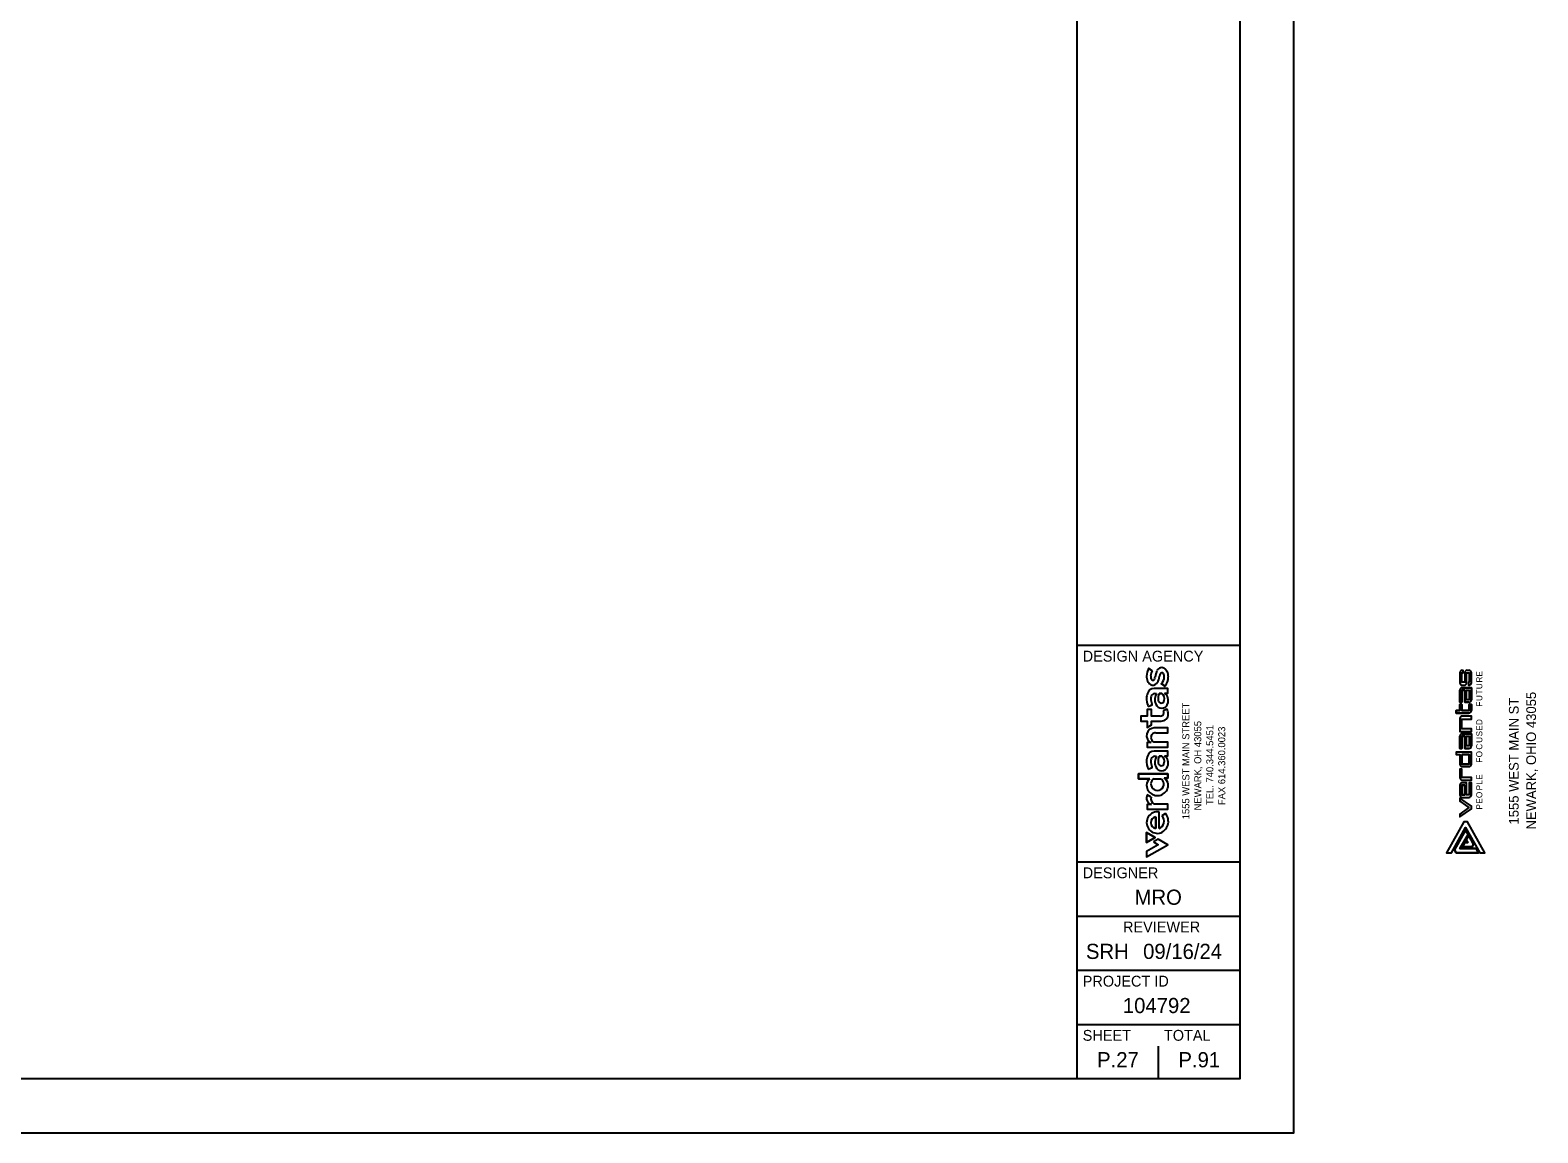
# Model space of a CAD drawing. Extents: x 0 to 36.3, y 0 to 22.
# Drawn here: x 22.33 to 36.25, y 0 to 10.18 of the extents above; entities that cross this region are included whole.
import ezdxf

# ---------------------------------------------------------------- set-up
doc = ezdxf.new("R2010")
doc.units = 0
for name, color, linetype in [('CS-ANNO-TTLB-LOGO', 7, 'Continuous'), ('Default', 7, 'Continuous'), ('SH_Border', 7, 'Continuous'), ('SH_Cut_Line', 7, 'Continuous'), ('SH_Data', 7, 'Continuous'), ('SH_Text', 7, 'Continuous')]:
    doc.layers.add(name, color=color, linetype=linetype)

msp = doc.modelspace()

# ---------------------------------------------------------------- linework, layer by layer
at = {"layer": 'CS-ANNO-TTLB-LOGO'}
for p, q in [((35.533, 4.247), (35.533, 4.154)), ((35.564, 4.269), (35.555, 4.269)), ((35.617, 4.269), (35.6, 4.269)), ((35.64, 4.154), (35.64, 4.247)), ((35.533, 3.974), (35.533, 4.086)), ((35.555, 4.131), (35.572, 4.131)), ((35.533, 3.549), (35.533, 3.661)), ((35.555, 3.38), (35.617, 3.38)), ((35.533, 3.209), (35.533, 3.119)), ((35.64, 3.119), (35.64, 3.231)), ((35.555, 3.096), (35.617, 3.096))]:
    msp.add_line(p, q, dxfattribs=at)
for points in [[(35.578, 4.247), (35.578, 4.159), (35.552, 4.159), (35.552, 4.247), (35.564, 4.247), (35.564, 4.269)], [(35.595, 4.154), (35.595, 4.247), (35.62, 4.247), (35.62, 4.159), (35.611, 4.159), (35.611, 4.131), (35.617, 4.131)], [(35.617, 3.974), (35.578, 3.974), (35.578, 4.086), (35.552, 4.086), (35.552, 3.974), (35.533, 3.974)], [(35.555, 4.109), (35.64, 4.109), (35.64, 3.996)], [(35.498, 3.898), (35.533, 3.898), (35.533, 3.954), (35.552, 3.954), (35.552, 3.898), (35.62, 3.898), (35.62, 3.954), (35.64, 3.954), (35.64, 3.898)], [(35.617, 3.875), (35.498, 3.875), (35.498, 3.898)], [(35.533, 3.825), (35.533, 3.706), (35.64, 3.706), (35.64, 3.729), (35.552, 3.729), (35.552, 3.819), (35.64, 3.819)], [(35.64, 3.819), (35.64, 3.847), (35.555, 3.847)], [(35.617, 3.549), (35.578, 3.549), (35.578, 3.661), (35.552, 3.661), (35.552, 3.549), (35.533, 3.549)], [(35.555, 3.684), (35.64, 3.684), (35.64, 3.571)], [(35.498, 3.515), (35.498, 3.493), (35.533, 3.493), (35.533, 3.403)], [(35.64, 3.403), (35.64, 3.515), (35.498, 3.515)], [(35.64, 3.279), (35.552, 3.279), (35.552, 3.358), (35.533, 3.358), (35.533, 3.279)], [(35.555, 3.256), (35.64, 3.256), (35.64, 3.279)], [(35.64, 3.231), (35.62, 3.231), (35.62, 3.119), (35.595, 3.119), (35.595, 3.231), (35.555, 3.231)]]:
    msp.add_lwpolyline(points, dxfattribs=at)
for points in [[(35.595, 4.086), (35.62, 4.086), (35.62, 3.996), (35.595, 3.996)], [(35.595, 3.661), (35.62, 3.661), (35.62, 3.571), (35.595, 3.571)], [(35.552, 3.493), (35.552, 3.403), (35.62, 3.403), (35.62, 3.493)], [(35.578, 3.209), (35.552, 3.209), (35.552, 3.119), (35.578, 3.119)], [(35.617, 3.002), (35.533, 2.943), (35.533, 2.916), (35.64, 2.991), (35.64, 3.014), (35.533, 3.089), (35.533, 3.062)]]:
    msp.add_lwpolyline(points, close=True, dxfattribs=at)
for centre, start, end in [((35.555, 4.247), 90, 180), ((35.6, 4.247), 90, 180), ((35.617, 4.247), 360, 90), ((35.555, 4.154), 180, 270), ((35.555, 4.086), 90, 180), ((35.572, 4.154), 270, 0), ((35.617, 4.154), 270, 0), ((35.617, 3.996), 270, 360), ((35.555, 3.825), 90, 180), ((35.617, 3.898), 270, 360), ((35.555, 3.661), 90, 180), ((35.617, 3.571), 270, 360), ((35.555, 3.403), 180, 270), ((35.617, 3.403), 270, 0), ((35.555, 3.279), 180, 270), ((35.555, 3.209), 90, 180), ((35.555, 3.119), 180, 270), ((35.617, 3.119), 270, 0)]:
    msp.add_arc(centre, 0.0225, start, end, dxfattribs=at)
at = {"layer": 'Default'}
for p, q in [((35.533, 4.247), (35.533, 4.154)), ((35.617, 4.269), (35.6, 4.269)), ((35.64, 4.154), (35.64, 4.247)), ((35.555, 4.131), (35.572, 4.131)), ((35.555, 3.38), (35.617, 3.38)), ((35.533, 3.209), (35.533, 3.119)), ((35.555, 3.096), (35.617, 3.096)), ((35.482, 2.612), (35.586, 2.795)), ((35.586, 2.795), (35.608, 2.755)), ((35.608, 2.755), (35.534, 2.624)), ((35.498, 2.585), (35.482, 2.612)), ((35.705, 2.585), (35.498, 2.585)), ((35.534, 2.624), (35.682, 2.624)), ((35.682, 2.624), (35.705, 2.585))]:
    msp.add_line(p, q, dxfattribs=at)
for points in [[(35.578, 4.247), (35.578, 4.159), (35.552, 4.159), (35.552, 4.247), (35.564, 4.247), (35.564, 4.269), (35.555, 4.269)], [(35.595, 4.154), (35.595, 4.247), (35.62, 4.247), (35.62, 4.159), (35.611, 4.159), (35.611, 4.131), (35.617, 4.131)], [(35.533, 4.086), (35.533, 3.974), (35.552, 3.974), (35.552, 4.086), (35.578, 4.086), (35.578, 3.974), (35.617, 3.974)], [(35.64, 3.996), (35.64, 4.109), (35.555, 4.109)], [(35.64, 3.898), (35.64, 3.954), (35.62, 3.954), (35.62, 3.898), (35.552, 3.898), (35.552, 3.954), (35.533, 3.954), (35.533, 3.898), (35.498, 3.898), (35.498, 3.875), (35.617, 3.875)], [(35.533, 3.825), (35.533, 3.706), (35.64, 3.706), (35.64, 3.729), (35.552, 3.729), (35.552, 3.819), (35.64, 3.819), (35.64, 3.847), (35.555, 3.847)], [(35.533, 3.661), (35.533, 3.549), (35.552, 3.549), (35.552, 3.661), (35.578, 3.661), (35.578, 3.549), (35.617, 3.549)], [(35.64, 3.571), (35.64, 3.684), (35.555, 3.684)], [(35.64, 3.403), (35.64, 3.515), (35.498, 3.515), (35.498, 3.493), (35.533, 3.493), (35.533, 3.403)], [(35.555, 3.256), (35.64, 3.256), (35.64, 3.279), (35.552, 3.279), (35.552, 3.358), (35.533, 3.358), (35.533, 3.279)], [(35.64, 3.119), (35.64, 3.231), (35.62, 3.231), (35.62, 3.119), (35.595, 3.119), (35.595, 3.231), (35.555, 3.231)]]:
    msp.add_lwpolyline(points, dxfattribs=at)
for points in [[(35.62, 4.086), (35.62, 3.996), (35.595, 3.996), (35.595, 4.086)], [(35.62, 3.661), (35.62, 3.571), (35.595, 3.571), (35.595, 3.661)], [(35.552, 3.493), (35.62, 3.493), (35.62, 3.403), (35.552, 3.403)], [(35.578, 3.209), (35.578, 3.119), (35.552, 3.119), (35.552, 3.209)], [(35.533, 2.943), (35.533, 2.916), (35.64, 2.991), (35.64, 3.014), (35.533, 3.089), (35.533, 3.062), (35.617, 3.002)], [(35.586, 2.818), (35.717, 2.585), (35.763, 2.585), (35.602, 2.87), (35.569, 2.87), (35.408, 2.585), (35.454, 2.585)], [(35.454, 2.585), (35.586, 2.818), (35.717, 2.585), (35.763, 2.585), (35.602, 2.87), (35.569, 2.87), (35.408, 2.585)], [(35.482, 2.612), (35.498, 2.585), (35.705, 2.585), (35.682, 2.624), (35.534, 2.624), (35.608, 2.755), (35.586, 2.795)], [(35.579, 2.68), (35.556, 2.641), (35.647, 2.641), (35.66, 2.664), (35.615, 2.744), (35.592, 2.704), (35.605, 2.68)], [(35.579, 2.68), (35.605, 2.68), (35.592, 2.704), (35.615, 2.744), (35.66, 2.664), (35.647, 2.641), (35.556, 2.641)]]:
    msp.add_lwpolyline(points, close=True, dxfattribs=at)
for centre, start, end in [((35.555, 4.247), 90, 180), ((35.6, 4.247), 90, 180), ((35.617, 4.247), 360, 90), ((35.555, 4.154), 180, 270), ((35.555, 4.086), 90, 180), ((35.572, 4.154), 270, 0), ((35.617, 4.154), 270, 0), ((35.617, 3.996), 270, 0), ((35.555, 3.825), 90, 180), ((35.617, 3.898), 270, 0), ((35.555, 3.661), 90, 180), ((35.617, 3.571), 270, 0), ((35.555, 3.403), 180, 270), ((35.617, 3.403), 270, 0), ((35.555, 3.279), 180, 270), ((35.555, 3.209), 90, 180), ((35.555, 3.119), 180, 270), ((35.617, 3.119), 270, 0)]:
    msp.add_arc(centre, 0.0225, start, end, dxfattribs=at)
at = {"layer": 'SH_Border'}
for p, q in [((32, 0.5), (32, 21.5)), ((32, 4.5), (33.5, 4.5)), ((32, 2.5), (33.5, 2.5)), ((32, 2), (33.5, 2)), ((32, 1.5), (33.5, 1.5)), ((32, 1), (33.5, 1))]:
    msp.add_line(p, q, dxfattribs=at)
msp.add_lwpolyline([(1.5, 21.5), (33.5, 21.5), (33.5, 0.5), (1.5, 0.5)], close=True, dxfattribs=at)
at = {"layer": 'SH_Cut_Line'}
msp.add_lwpolyline([(0, 0), (34, 0), (34, 22), (0, 22)], close=True, dxfattribs=at)
at = {"layer": 'SH_Data'}
for p, q in [((32.75, 3.5), (32.75, 3.5)), ((32.75, 0.5), (32.75, 0.8)), ((32.375, 0.675), (32.375, 0.675))]:
    msp.add_line(p, q, dxfattribs=at)
at = {"layer": 'SH_Text'}
for p, q in [((32.692, 4.264), (32.661, 4.287)), ((32.726, 4.238), (32.72, 4.207)), ((32.755, 4.196), (32.76, 4.216)), ((32.715, 4.056), (32.731, 4.056)), ((32.757, 4.056), (32.78, 4.056)), ((32.778, 4.148), (32.811, 4.124)), ((32.652, 3.948), (32.656, 3.936)), ((32.829, 3.912), (32.794, 3.896)), ((32.652, 3.369), (32.656, 3.357)), ((32.715, 3.477), (32.731, 3.477)), ((32.757, 3.477), (32.78, 3.477)), ((32.71, 3.269), (32.77, 3.269)), ((32.683, 3.098), (32.646, 3.12)), ((32.755, 2.809), (32.755, 2.962)), ((32.815, 2.947), (32.782, 2.925)), ((32.725, 2.917), (32.725, 2.81))]:
    msp.add_line(p, q, dxfattribs=at)
for points in [[(32.694, 4.266), (32.662, 4.289), (32.661, 4.287)], [(32.692, 4.264), (32.694, 4.266)], [(32.726, 4.238), (32.72, 4.207)], [(32.755, 4.196), (32.76, 4.216)], [(32.805, 4.059), (32.835, 4.059), (32.835, 4.101), (32.71, 4.101)], [(32.805, 4.059), (32.835, 4.059), (32.835, 4.101), (32.71, 4.101)], [(32.715, 4.056), (32.731, 4.056)], [(32.78, 4.056), (32.757, 4.056)], [(32.778, 4.148), (32.776, 4.146), (32.807, 4.121), (32.811, 4.124)], [(32.766, 3.846), (32.684, 3.846), (32.684, 3.907), (32.645, 3.907), (32.645, 3.846), (32.587, 3.846), (32.587, 3.801), (32.645, 3.801), (32.645, 3.741), (32.684, 3.765), (32.684, 3.801), (32.774, 3.801)], [(32.766, 3.846), (32.684, 3.846), (32.684, 3.907), (32.645, 3.907), (32.645, 3.846), (32.587, 3.846), (32.587, 3.801), (32.645, 3.801), (32.645, 3.741), (32.684, 3.765), (32.684, 3.801), (32.774, 3.801)], [(32.652, 3.948), (32.656, 3.936)], [(32.656, 3.936), (32.692, 3.95), (32.688, 3.96)], [(32.656, 3.936), (32.692, 3.95), (32.688, 3.96)], [(32.829, 3.912), (32.794, 3.896)], [(32.724, 3.692), (32.835, 3.692), (32.835, 3.737), (32.711, 3.737)], [(32.724, 3.692), (32.835, 3.692), (32.835, 3.737), (32.711, 3.737)], [(32.682, 3.603), (32.645, 3.603), (32.645, 3.56), (32.835, 3.56), (32.835, 3.606), (32.708, 3.606)], [(32.682, 3.603), (32.645, 3.603), (32.645, 3.56), (32.835, 3.56), (32.835, 3.606), (32.708, 3.606)], [(32.805, 3.481), (32.835, 3.481), (32.835, 3.523), (32.71, 3.523)], [(32.805, 3.481), (32.835, 3.481), (32.835, 3.523), (32.71, 3.523)], [(32.652, 3.369), (32.656, 3.357)], [(32.656, 3.357), (32.692, 3.372), (32.688, 3.381)], [(32.656, 3.357), (32.692, 3.372), (32.688, 3.381)], [(32.715, 3.477), (32.731, 3.477)], [(32.78, 3.477), (32.757, 3.477)], [(32.671, 3.269), (32.564, 3.269), (32.564, 3.314), (32.835, 3.314), (32.835, 3.273), (32.802, 3.273)], [(32.802, 3.273), (32.835, 3.273), (32.835, 3.314), (32.564, 3.314), (32.564, 3.269), (32.671, 3.269)], [(32.71, 3.269), (32.77, 3.269)], [(32.683, 3.098), (32.646, 3.12)], [(32.686, 3.03), (32.645, 3.03), (32.645, 2.989), (32.835, 2.989), (32.835, 3.033), (32.709, 3.033)], [(32.686, 3.03), (32.645, 3.03), (32.645, 2.989), (32.835, 2.989), (32.835, 3.033), (32.709, 3.033)], [(32.755, 2.809), (32.755, 2.962)], [(32.815, 2.947), (32.782, 2.925)], [(32.725, 2.81), (32.725, 2.917)], [(32.64, 2.772), (32.64, 2.681), (32.718, 2.727), (32.64, 2.772)], [(32.704, 2.685), (32.748, 2.659), (32.64, 2.597), (32.64, 2.547), (32.835, 2.659), (32.747, 2.71), (32.704, 2.685)]]:
    msp.add_lwpolyline(points, dxfattribs=at)
for points in [[(32.718, 2.727), (32.64, 2.681), (32.64, 2.772)], [(32.704, 2.685), (32.748, 2.659), (32.64, 2.597), (32.64, 2.547), (32.835, 2.659), (32.747, 2.71)]]:
    msp.add_lwpolyline(points, close=True, dxfattribs=at)
for centre, radius, start, end in [((32.771, 4.216), 0.131, 147.2233, 179.842), ((32.771, 4.216), 0.131, 147.2233, 179.842), ((32.754, 4.215), 0.114, 179.0109, 203.56), ((32.754, 4.215), 0.114, 179.0109, 203.56), ((32.772, 4.214), 0.0948, 148.1233, 178.1135), ((32.772, 4.214), 0.0948, 148.1233, 178.1135), ((32.748, 4.216), 0.0702, 179.0539, 195.6921), ((32.748, 4.216), 0.0702, 179.0539, 195.6921), ((32.713, 4.205), 0.0335, 193.8561, 223.7191), ((32.713, 4.205), 0.0335, 193.8561, 223.7191), ((32.699, 4.192), 0.0148, 224.7822, 330.4366), ((32.699, 4.192), 0.0148, 224.7822, 330.4366), ((32.639, 4.222), 0.0819, 332.9002, 349.3831), ((32.639, 4.222), 0.0819, 332.9002, 349.3831), ((32.853, 4.209), 0.13, 154.0447, 167.2149), ((32.853, 4.209), 0.13, 154.0447, 167.2149), ((32.652, 4.215), 0.105, 320.1259, 349.7023), ((32.652, 4.215), 0.105, 320.1259, 349.7023), ((32.781, 4.245), 0.0493, 52.7092, 154.2166), ((32.781, 4.245), 0.0493, 52.7092, 154.2166), ((32.853, 4.201), 0.0949, 158.1863, 170.6328), ((32.853, 4.201), 0.0949, 158.1863, 170.6328), ((32.781, 4.231), 0.0165, 26.9165, 163.602), ((32.781, 4.231), 0.0165, 26.9165, 163.602), ((32.71, 4.211), 0.0932, 317.363, 356.9244), ((32.71, 4.211), 0.0932, 317.363, 356.9244), ((32.737, 4.21), 0.0655, 357.0077, 26.3112), ((32.737, 4.21), 0.0655, 357.0077, 26.3112), ((32.765, 4.229), 0.0711, 22.8278, 50.7157), ((32.765, 4.229), 0.0711, 22.8278, 50.7157), ((32.711, 4.207), 0.129, 320.5166, 0.4341), ((32.711, 4.207), 0.129, 320.5166, 0.4341), ((32.721, 4.21), 0.12, 359.0192, 22.9257), ((32.721, 4.21), 0.12, 359.0192, 22.9257), ((32.768, 4.014), 0.128, 160.8128, 180.9317), ((32.768, 4.014), 0.128, 160.8128, 180.9317), ((32.708, 4.037), 0.0639, 88.076, 162.8642), ((32.708, 4.037), 0.0639, 88.076, 162.8642), ((32.711, 4.196), 0.067, 203.3692, 237.807), ((32.711, 4.196), 0.067, 203.3692, 237.807), ((32.699, 4.178), 0.0458, 238.9453, 317.6829), ((32.699, 4.178), 0.0458, 238.9453, 317.6829), ((32.717, 4.018), 0.0374, 92.9671, 165.223), ((32.717, 4.018), 0.0374, 92.9671, 165.223), ((32.824, 3.999), 0.108, 148.3497, 202.4708), ((32.824, 3.999), 0.108, 148.3497, 202.4708), ((32.851, 4.009), 0.105, 153.8372, 188.8746), ((32.851, 4.009), 0.105, 153.8372, 188.8746), ((32.741, 4.005), 0.0637, 348.1247, 52.3678), ((32.741, 4.005), 0.0637, 348.1247, 52.3678), ((32.755, 3.99), 0.0857, 338.2774, 53.7949), ((32.755, 3.99), 0.0857, 338.2774, 53.7949), ((32.838, 4.015), 0.199, 180.9467, 199.8354), ((32.838, 4.015), 0.199, 180.9467, 199.8354), ((32.743, 4.009), 0.0647, 163.2522, 179.9971), ((32.743, 4.009), 0.0647, 163.2522, 179.9971), ((32.83, 4.014), 0.152, 181.6616, 200.8714), ((32.83, 4.014), 0.152, 181.6616, 200.8714), ((32.779, 3.979), 0.0592, 201.6764, 339.7268), ((32.779, 3.979), 0.0592, 201.6764, 339.7268), ((32.775, 3.994), 0.0281, 182.327, 355.3778), ((32.775, 3.994), 0.0281, 182.327, 355.3778), ((32.746, 3.868), 0.0939, 359.5424, 28.2495), ((32.746, 3.868), 0.0939, 359.5424, 28.2495), ((32.768, 3.878), 0.0314, 265.0692, 356.3548), ((32.768, 3.878), 0.0314, 265.0692, 356.3548), ((32.776, 3.865), 0.0642, 267.8641, 1.6213), ((32.776, 3.865), 0.0642, 267.8641, 1.6213), ((32.757, 3.874), 0.0432, 1.8638, 29.9651), ((32.757, 3.874), 0.0432, 1.8638, 29.9651), ((32.71, 3.667), 0.0703, 88.9896, 246.9111), ((32.71, 3.667), 0.0703, 88.9896, 246.9111), ((32.724, 3.651), 0.0434, 137.3049, 182.9688), ((32.724, 3.651), 0.0434, 137.3049, 182.9688), ((32.728, 3.649), 0.0477, 180.3466, 244.9113), ((32.728, 3.649), 0.0477, 180.3466, 244.9113), ((32.721, 3.649), 0.0433, 86.9739, 132.7421), ((32.721, 3.649), 0.0433, 86.9739, 132.7421), ((32.708, 3.459), 0.0639, 88.076, 162.8642), ((32.708, 3.459), 0.0639, 88.076, 162.8642), ((32.755, 3.412), 0.0857, 338.2774, 53.7949), ((32.755, 3.412), 0.0857, 338.2774, 53.7949), ((32.768, 3.435), 0.128, 160.8128, 180.9317), ((32.768, 3.435), 0.128, 160.8128, 180.9317), ((32.838, 3.437), 0.199, 180.9467, 199.8354), ((32.838, 3.437), 0.199, 180.9467, 199.8354), ((32.743, 3.431), 0.0647, 163.2522, 179.9971), ((32.743, 3.431), 0.0647, 163.2522, 179.9971), ((32.83, 3.435), 0.152, 181.6616, 200.8714), ((32.83, 3.435), 0.152, 181.6616, 200.8714), ((32.717, 3.44), 0.0374, 92.9671, 165.223), ((32.717, 3.44), 0.0374, 92.9671, 165.223), ((32.824, 3.42), 0.108, 148.3497, 202.4708), ((32.824, 3.42), 0.108, 148.3497, 202.4708), ((32.779, 3.401), 0.0592, 201.6764, 339.7268), ((32.779, 3.401), 0.0592, 201.6764, 339.7268), ((32.851, 3.431), 0.105, 153.8372, 188.8746), ((32.851, 3.431), 0.105, 153.8372, 188.8746), ((32.775, 3.416), 0.0281, 182.327, 355.3778), ((32.775, 3.416), 0.0281, 182.327, 355.3778), ((32.741, 3.427), 0.0637, 348.1247, 52.3678), ((32.741, 3.427), 0.0637, 348.1247, 52.3678), ((32.711, 3.21), 0.0714, 124.2843, 181.2723), ((32.711, 3.21), 0.0714, 124.2843, 181.2723), ((32.74, 3.213), 0.1, 182.7719, 2.9779), ((32.74, 3.213), 0.1, 182.7719, 2.9779), ((32.739, 3.218), 0.0586, 119.9007, 175.5797), ((32.739, 3.218), 0.0586, 119.9007, 175.5797), ((32.74, 3.219), 0.0595, 176.4529, 5.055), ((32.74, 3.219), 0.0595, 176.4529, 5.055), ((32.741, 3.218), 0.0588, 6.0666, 60.041), ((32.741, 3.218), 0.0588, 6.0666, 60.041), ((32.773, 3.212), 0.0671, 5.3084, 64.5252), ((32.773, 3.212), 0.0671, 5.3084, 64.5252), ((32.702, 3.091), 0.0628, 152.6524, 255.2929), ((32.702, 3.091), 0.0628, 152.6524, 255.2929), ((32.735, 3.081), 0.0545, 162.1384, 242.0408), ((32.735, 3.081), 0.0545, 162.1384, 242.0408), ((32.74, 2.864), 0.0996, 81.0446, 280.2577), ((32.74, 2.864), 0.0996, 81.0446, 280.2577), ((32.729, 2.876), 0.072, 290.9232, 42.7391), ((32.729, 2.876), 0.072, 290.9232, 42.7391), ((32.727, 2.875), 0.114, 285.6668, 39.3699), ((32.727, 2.875), 0.114, 285.6668, 39.3699), ((32.733, 2.863), 0.0543, 98.8378, 261.1622), ((32.733, 2.863), 0.0543, 98.8378, 261.1622)]:
    msp.add_arc(centre, radius, start, end, dxfattribs=at)

# ---------------------------------------------------------------- texts
at = {"layer": 'Default'}
for s, p in [('E', (35.74, 4.212)), ('R', (35.74, 4.156)), ('U', (35.74, 4.095)), ('T', (35.74, 4.046)), ('U', (35.74, 3.986)), ('F', (35.74, 3.934)), ('D', (35.74, 3.764)), ('S', (35.74, 3.659)), ('E', (35.74, 3.711)), ('U', (35.74, 3.6)), ('C', (35.74, 3.537)), ('O', (35.74, 3.466)), ('F', (35.74, 3.417)), ('E', (35.74, 3.259)), ('L', (35.74, 3.214)), ('P', (35.74, 3.161)), ('O', (35.74, 3.09)), ('E', (35.74, 3.037)), ('P', (35.74, 2.984))]:
    msp.add_text(s, height=0.0563, rotation=90, dxfattribs=at).set_placement(p)
at = {"layer": 'SH_Data'}
for s, height, p in [('DESIGN AGENCY', 0.1, (32.05, 4.35)), ('DESIGNER', 0.1, (32.05, 2.35)), ('MRO', 0.14, (32.529, 2.105)), ('REVIEWER', 0.1, (32.422, 1.85)), ('SRH', 0.14, (32.08, 1.605)), ('09/16/24', 0.14, (32.608, 1.605)), ('PROJECT ID', 0.1, (32.05, 1.35)), ('104792', 0.14, (32.421, 1.105)), ('SHEET', 0.1, (32.05, 0.85)), ('TOTAL', 0.1, (32.8, 0.85)), ('P.27', 0.14, (32.183, 0.605)), ('P.91', 0.14, (32.934, 0.605))]:
    msp.add_text(s, height=height, dxfattribs=at).set_placement(p)
at = {"layer": 'SH_Text'}
for s, height, p in [('NEWARK, OHIO 43055', 0.09, (36.236, 2.8)), ('1555 WEST MAIN STREET', 0.06497, (33.035, 2.894)), ('1555 WEST MAIN ST', 0.09, (36.076, 2.846)), ('NEWARK, OH 43055', 0.06497, (33.145, 2.976)), ('TEL. 740.344.5451', 0.06497, (33.256, 3.026)), ('FAX 614.360.0023', 0.06497, (33.366, 3.025))]:
    msp.add_text(s, height=height, rotation=90, dxfattribs=at).set_placement(p)

doc.saveas('drawing.dxf')
